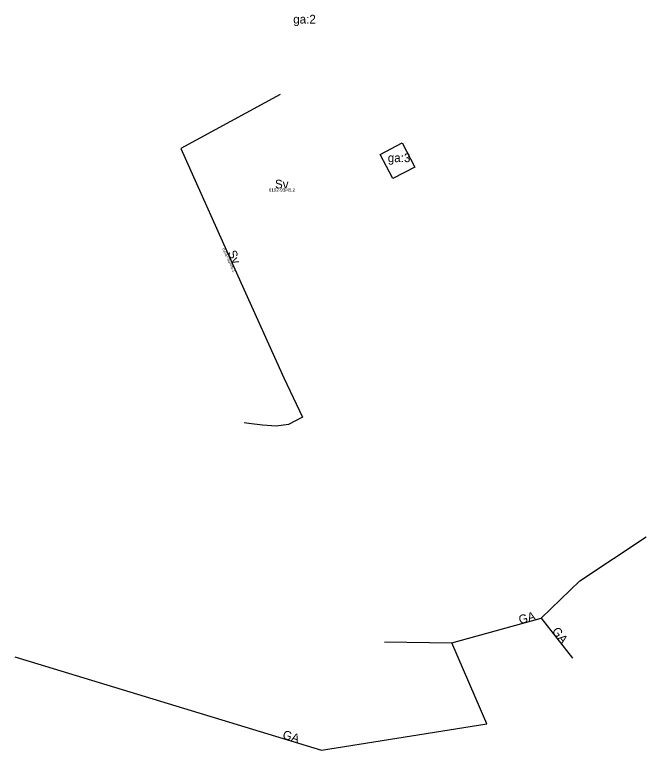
# Model space of a CAD drawing. Extents: x 140791 to 143631, y 6542790 to 6549933.
# Drawn here: x 141833.4 to 142088.2, y 6548922.2 to 6549218.9 of the extents above; entities that cross this region are included whole.
import ezdxf

# ---------------------------------------------------------------- set-up
doc = ezdxf.new("R2010")
doc.units = 0
for name, color, linetype in [('RATT Aktbeteckning för servitut', 7, 'Continuous'), ('RATT Beteckning för gemensammhetsanläggning', 7, 'Continuous'), ('RATT Beteckning för servitut', 7, 'Continuous'), ('RATT Gemensamhetsanläggning', 7, 'Continuous'), ('RATT Gemensamhetsanläggningsgräns', 7, 'Continuous'), ('RATT Servitut', 7, 'Continuous')]:
    doc.layers.add(name, color=color, linetype=linetype)

msp = doc.modelspace()

# ---------------------------------------------------------------- linework, layer by layer
at = {"layer": 'RATT Gemensamhetsanläggning'}
msp.add_line((142045.85, 6548975.43), (142058.41, 6548959.42), dxfattribs=at)
for points in [[(141982.61, 6548965.93), (142009.78, 6548965.54), (142045.85, 6548975.43), (142061.45, 6548990.53), (142088.2, 6549008.28)], [(141833.35, 6548959.9), (141957.19, 6548922.19), (142023.81, 6548932.87), (142009.78, 6548965.54)]]:
    msp.add_lwpolyline(points, dxfattribs=at)
at = {"layer": 'RATT Gemensamhetsanläggningsgräns'}
msp.add_lwpolyline([(141985.93, 6549152.87), (141980.84, 6549162.62), (141989.7, 6549167.25), (141994.79, 6549157.49), (141985.93, 6549152.87)], dxfattribs=at)
at = {"layer": 'RATT Servitut'}
msp.add_lwpolyline([(141940.53, 6549186.79), (141900.33, 6549164.96), (141923.45, 6549113.63), (141941.96, 6549072.45), (141949.53, 6549056.58), (141943.84, 6549053.59), (141938.91, 6549053), (141933.36, 6549053.4), (141927.76, 6549054.05), (141925.94, 6549054.26)], dxfattribs=at)

# ---------------------------------------------------------------- texts
at = {"layer": 'RATT Aktbeteckning för servitut'}
msp.add_text('0192-93/45.2', height=1.3, dxfattribs=at).set_placement((141935.91, 6549147.58))
msp.add_text('0192-93/45.1', height=1.3, rotation=294.5, dxfattribs=at).set_placement((141917.07, 6549124.59))
at = {"layer": 'RATT Beteckning för gemensammhetsanläggning'}
for s, p in [('ga:2', (141945.74, 6549215.4)), ('ga:3', (141983.91, 6549159.48))]:
    msp.add_text(s, height=3.5, dxfattribs=at).set_placement(p)
for rotation, p in [(15.47, (142037.25, 6548973.07)), (308.043, (142049.95, 6548970.21)), (343.202, (141941.17, 6548927.06))]:
    msp.add_text('GA', height=3.5, rotation=rotation, dxfattribs=at).set_placement(p)
at = {"layer": 'RATT Beteckning för servitut'}
msp.add_text('Sv', height=3.5, dxfattribs=at).set_placement((141938.38, 6549148.88))
msp.add_text('Sv', height=3.5, rotation=294.5, dxfattribs=at).set_placement((141919.23, 6549122.98))

doc.saveas('drawing.dxf')
